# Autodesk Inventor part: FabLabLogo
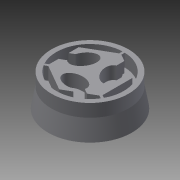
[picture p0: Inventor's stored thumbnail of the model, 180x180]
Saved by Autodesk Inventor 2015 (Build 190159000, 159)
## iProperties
Created: 2015-04
Part Number: FabLabLogo
Material: Generic
Document SubType Name: Modeling
Designer: User
Density: 1 g/cm^3
Appearance: Default
Author: User
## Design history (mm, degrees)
sketch "Sketch1"
  geometry: L1 (7.305, 13.346)-(7.305, 12.813); L2 (7.305, 13.346)-(7.305, 12.813); L3 (8.744, 12.189)-(7.657, 12.817); L4 (7.305, 12.813)-(3.299, 10.501); L5 (3.299, 10.501)-(3.299, 8.898); L6 (7.305, 12.813)-(3.299, 10.501); L7 (8.874, 4.055)-(8.261, 4.403); L8 (7.484, 3.253)-(8.874, 4.055); L9 (3.299, 8.898)-(3.999, 9.304); L10 (3.299, 8.898)-(3.999, 9.304); L11 (3.299, 10.501)-(3.299, 8.898); L12 (9.437, 5.306)-(10.237, 4.842); L13 (12.132, 5.597)-(11.669, 5.864); L14 (11.669, 5.864)-(11.669, 10.501); L15 (11.669, 5.864)-(11.669, 10.501); L16 (11.669, 10.501)-(10.403, 11.231); L17 (9.437, 5.306)-(10.237, 4.842); L18 (10.237, 4.842)-(11.486, 5.563); L19 (8.874, 4.055)-(8.261, 4.403); L20 (7.484, 3.253)-(8.874, 4.055); L21 (3.48, 5.564)-(7.484, 3.253); L22 (3.48, 5.564)-(7.484, 3.253); L23 (4.172, 7.828)-(3.299, 7.333); L24 (3.299, 7.333)-(3.299, 5.867); L25 (3.299, 5.867)-(2.835, 5.599); L26 (3.299, 5.867)-(2.835, 5.599); L27 (4.172, 7.828)-(3.299, 7.333); L28 (3.299, 7.333)-(3.299, 5.867); L29 (7.657, 12.817)-(7.657, 13.346); L30 (8.744, 10.953)-(8.744, 12.189); L31 (8.744, 10.953)-(8.744, 12.189); L32 (8.744, 12.189)-(7.657, 12.817); L33 (7.657, 12.817)-(7.657, 13.346); L34 (10.403, 11.231)-(10.403, 10.268); L35 (10.403, 11.231)-(10.403, 10.268); L36 (10.237, 4.842)-(11.486, 5.563); L37 (11.669, 10.501)-(10.403, 11.231); L38 (12.132, 5.597)-(11.669, 5.864); L39 (7.305, 13.346)-(7.305, 12.813); L40 (7.305, 13.346)-(7.305, 12.813); L41 (8.744, 12.189)-(7.657, 12.817); L42 (7.305, 12.813)-(3.299, 10.501); L43 (3.299, 10.501)-(3.299, 8.898); L44 (7.305, 12.813)-(3.299, 10.501); L45 (8.874, 4.055)-(8.261, 4.403); L46 (7.484, 3.253)-(8.874, 4.055); L47 (3.299, 8.898)-(3.999, 9.304); L48 (3.299, 8.898)-(3.999, 9.304); L49 (3.299, 10.501)-(3.299, 8.898); L50 (9.437, 5.306)-(10.237, 4.842); L51 (12.132, 5.597)-(11.669, 5.864); L52 (11.669, 5.864)-(11.669, 10.501); L53 (11.669, 5.864)-(11.669, 10.501); L54 (11.669, 10.501)-(10.403, 11.231); L55 (9.437, 5.306)-(10.237, 4.842); L56 (10.237, 4.842)-(11.486, 5.563); L57 (8.874, 4.055)-(8.261, 4.403); L58 (7.484, 3.253)-(8.874, 4.055); L59 (3.48, 5.564)-(7.484, 3.253); L60 (3.48, 5.564)-(7.484, 3.253); L61 (4.172, 7.828)-(3.299, 7.333); L62 (3.299, 7.333)-(3.299, 5.867); L63 (3.299, 5.867)-(2.835, 5.599); L64 (3.299, 5.867)-(2.835, 5.599)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; C1 r 6.026 at (7.483, 8.076); 48 further points
  constraints: 152 end point, 1 centre point, 192 other
extrude "Extrusion1" new body sketch "Sketch1" distance "d0" = 2; taper "d1" = 0 deg
sketch "Sketch8"
  geometry: C1 r 6.026 at (-7.484, 8.077); 2 further points
  constraints: 1 centre point, 1 other
extrude "Extrusion2" join sketch "Sketch8" distance "d3" = 3; taper "d4" = 10 deg
body "Solid1"
